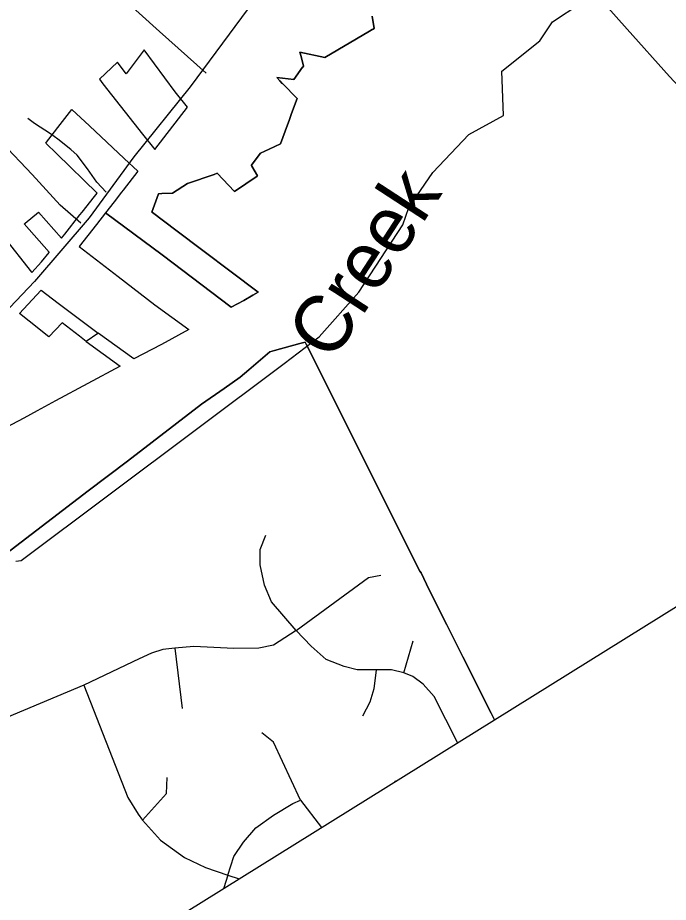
# Model space of a CAD drawing. Extents: x 2001466 to 31450019, y -30647475 to 847247.
# Drawn here: x 31439858 to 31443289, y -30638655 to -30633991 of the extents above; entities that cross this region are included whole.
import ezdxf

# ---------------------------------------------------------------- set-up
doc = ezdxf.new("R2010")
doc.units = 0
for name, color, linetype in [('Exist Boundary Political City Limit New', 7, 'Continuous'), ('Exist Boundary Political City Limit New Hole', 7, 'Continuous'), ('Exist Hydrographic Creek Single Shore', 7, 'Continuous'), ('Exist Hydrographic Creek Single Shore Label', 7, 'Continuous'), ('Exist Road Non-System Type 51', 7, 'Continuous'), ('Exist Road Secondary Type 51 Attributed', 7, 'Continuous'), ('Map Preparation Boundary City Limit Buffer Line', 7, 'Continuous')]:
    doc.layers.add(name, color=color, linetype=linetype)

msp = doc.modelspace()

# ---------------------------------------------------------------- linework, layer by layer
at = {"layer": 'Exist Boundary Political City Limit New'}
for points in [[(31442371.7, -30637692.6), (31450018.8, -30632929.3), (31449005.2, -30631302)], [(31441727.3, -30633982.6), (31441736.9, -30634048.1), (31441729.1, -30634052.7), (31441727.8, -30634053.5), (31441712.5, -30634062.5), (31441478.3, -30634200.5), (31441346.1, -30634172.8), (31441352.3, -30634196), (31441365.3, -30634245.8), (31441361.5, -30634251.1), (31441360.5, -30634252.3), (31441313.5, -30634317.4), (31441224.1, -30634306.8), (31441240, -30634323.2), (31441253.3, -30634336.9), (31441253.8, -30634337.5), (31441330.8, -30634417.4), (31441302, -30634496.6), (31441288.9, -30634532.5), (31441280.3, -30634556.4), (31441244.4, -30634655.1), (31441183.5, -30634684.1), (31441138.8, -30634705.5), (31441089.6, -30634769.3), (31441091.5, -30634772.6), (31441092.1, -30634773.6), (31441122, -30634824.6), (31441120.9, -30634825.5), (31441120.1, -30634826), (31441001, -30634907.8), (31440910.6, -30634811.3), (31440894, -30634816.9), (31440753.4, -30634864.3), (31440674.6, -30634915.6), (31440617.8, -30634918.4), (31440601.3, -30634919.1), (31440566.1, -30635016.3), (31440568.1, -30635017.8), (31440569.3, -30635018.6), (31440691, -30635110.8), (31441126, -30635438.1), (31441098, -30635454), (31441049.6, -30635481.5), (31440983.1, -30635516.6), (31440619.9, -30635241.8), (31440321.5, -30635019.1)], [(31440321.5, -30635019.1), (31440273.5, -30635080.9), (31440228.3, -30635139.1), (31440182.4, -30635197.6), (31440388.6, -30635355.6), (31440581.3, -30635505), (31440759.6, -30635635.8), (31440615.4, -30635714), (31440470.1, -30635790.3), (31440283.1, -30635654.7)], [(31440219.9, -30635698.3), (31440218.8, -30635697.5), (31440183.3, -30635670.6), (31440092, -30635599.9), (31440021.6, -30635674.3), (31439918.1, -30635591.6), (31439866.9, -30635550.6), (31439933.9, -30635479), (31439982.4, -30635427.1), (31440071.5, -30635495.8)], [(31440071.5, -30635495.8), (31440275.8, -30635649.2), (31440283.1, -30635654.7)], [(31440283.1, -30635654.7), (31440280.6, -30635656.8), (31440219.9, -30635698.3)], [(31440283.1, -30635654.7), (31440280.6, -30635656.8), (31440219.9, -30635698.3)], [(31440219.9, -30635698.3), (31440397.5, -30635828.4), (31440057.9, -30636011.1), (31439961.4, -30636063.5), (31439889.5, -30636102.2), (31439606.1, -30636252.6), (31439183.6, -30636480)], [(31439738.4, -30636859.9), (31440229.4, -30636486.1), (31440436.1, -30636328.8), (31440827.3, -30636029.1), (31440945.9, -30635946.1), (31441031.1, -30635886.5), (31441076.3, -30635847.9), (31441188, -30635752.2), (31441212, -30635745.6), (31441344.9, -30635708.8), (31441373.5, -30635700.9), (31441379.3, -30635712.5), (31441450.9, -30635855.5), (31441623.4, -30636200.1), (31441764.4, -30636481.2), (31441884.3, -30636720.6), (31441978.5, -30636908.8), (31441985.4, -30636918.8), (31442028, -30637007.8), (31442120.5, -30637192.3), (31442205.3, -30637361.5), (31442260.8, -30637471.8), (31442309.1, -30637568.2), (31442354.1, -30637657.6), (31442371.7, -30637692.6)]]:
    msp.add_lwpolyline(points, dxfattribs=at)
at = {"layer": 'Exist Boundary Political City Limit New Hole'}
msp.add_lwpolyline([(31440524.4, -30634160.1), (31440430.6, -30634286.6), (31440384.9, -30634225.8), (31440288.5, -30634315.6), (31440307, -30634340.1), (31440516.3, -30634605.1), (31440580.3, -30634685.9), (31440752.8, -30634462), (31440688.3, -30634381.6), (31440524.4, -30634160.1)], dxfattribs=at)
at = {"layer": 'Exist Hydrographic Creek Single Shore'}
for points in [[(31442411.4, -30634272.9), (31442611.3, -30634113), (31442678.4, -30634012.6), (31442827.5, -30633914)], [(31441888.5, -30635082.5), (31441921.3, -30634991.3), (31442046.4, -30634806.8), (31442237.5, -30634607.3), (31442420.4, -30634506.1), (31442411.4, -30634272.9)], [(31441262.3, -30635813.4), (31441448.5, -30635673.9), (31441656.4, -30635438.7), (31441888.5, -30635082.5)], [(31439849, -30636856.7), (31439875.5, -30636852.5), (31441262.3, -30635813.4)]]:
    msp.add_lwpolyline(points, dxfattribs=at)
at = {"layer": 'Exist Road Non-System Type 51'}
for points in [[(31439889.6, -30633577), (31439903.5, -30633567.1), (31439954.6, -30633548.8), (31439988.5, -30633544.5), (31440014.3, -30633550), (31440093.4, -30633598), (31440193.9, -30633688), (31440373.9, -30633853.5), (31440606.2, -30634063), (31440851.1, -30634282.9)], [(31440190.1, -30635074.9), (31440081.1, -30634979.4), (31439934.4, -30634818.4), (31439773.8, -30634649.1), (31439656.4, -30634524.7)], [(31440324.4, -30634911.2), (31440275.4, -30634858.2), (31440226.9, -30634787.2), (31440172.3, -30634716.1), (31440139, -30634685.4), (31440070.1, -30634632), (31440030.7, -30634603.2), (31439945.8, -30634549.5), (31439912.3, -30634522.8)], [(31441327, -30637221.7), (31441196.6, -30637071.1), (31441159, -30636983.2), (31441136.4, -30636875.3), (31441136.4, -30636795), (31441166.5, -30636719.7)], [(31441327, -30637221.7), (31441708.2, -30636943.1), (31441773.4, -30636930.5)], [(31441327, -30637221.7), (31441206.6, -30637299.4), (31441128.9, -30637314.5), (31440998.5, -30637317), (31440786.3, -30637307), (31440686, -30637314.5)], [(31441748.3, -30637429.9), (31441648, -30637429.9), (31441580.3, -30637412.4), (31441485, -30637374.7), (31441404.7, -30637304.5), (31441327, -30637221.7)], [(31441893.8, -30637445), (31441943.9, -30637276.9)], [(31440686, -30637314.5), (31440623.3, -30637322), (31440563.1, -30637342.1), (31440497.9, -30637372.2), (31440206.5, -30637510.3)], [(31440686, -30637314.5), (31440726.1, -30637633.2)], [(31441748.3, -30637429.9), (31441735.8, -30637530.3), (31441715.7, -30637600.6), (31441675.6, -30637673.4)], [(31441893.8, -30637445), (31441828.6, -30637429.9), (31441748.3, -30637429.9)], [(31442177.3, -30637813.6), (31442054.3, -30637570.5), (31441996.6, -30637505.2), (31441941.4, -30637465.1), (31441893.8, -30637445)], [(31440206.5, -30637510.3), (31439657.3, -30637741.1), (31439574.5, -30637768.7), (31439476.7, -30637798.9), (31439239.5, -30637845)], [(31440206.5, -30637510.3), (31440438.7, -30638102.5), (31440493.9, -30638190.4), (31440516.4, -30638223)], [(31441349.1, -30638117.6), (31441206.1, -30637811.4), (31441145.9, -30637761.2)], [(31440516.4, -30638223), (31440641.8, -30638082.4), (31440646.9, -30637997.1)], [(31441849.5, -30638017.8), (31441846.1, -30638014.7)], [(31440965.4, -30638511.6), (31440998, -30638413.7), (31441048.1, -30638338.4), (31441113.3, -30638263.1), (31441206.1, -30638195.4), (31441308.9, -30638135.2), (31441349.1, -30638117.6)], [(31441349.1, -30638117.6), (31441460.2, -30638260.3)], [(31440516.4, -30638223), (31440611.7, -30638328.4), (31440737.1, -30638418.7), (31440847.5, -30638471.4), (31440965.4, -30638511.6)], [(31440965.4, -30638511.6), (31440944.3, -30638579.4), (31440944, -30638581.9)], [(31440965.4, -30638511.6), (31441025.1, -30638531.3)]]:
    msp.add_lwpolyline(points, dxfattribs=at)
at = {"layer": 'Exist Road Secondary Type 51 Attributed'}
for points in [[(31441775.8, -30632944.3), (31441663.1, -30633133.5), (31441421.7, -30633512), (31441072.5, -30633942.8), (31440768.3, -30634355.1), (31440470.6, -30634724.7), (31440235.6, -30635046.8), (31439945.9, -30635381.8), (31439587, -30635759.4), (31439419.6, -30635923.7), (31439113.9, -30636184.6), (31438904.6, -30636324.7), (31438702.3, -30636439.9), (31438554.9, -30636541.1)], [(31441775.8, -30632944.3), (31442248.9, -30633253.5), (31442475.6, -30633406.6), (31442627.1, -30633553.8), (31442739.7, -30633676.8), (31443072.2, -30634050.8), (31443294.5, -30634301.4), (31443468.2, -30634486.4), (31443851, -30634906.2), (31444296, -30635391.3)]]:
    msp.add_lwpolyline(points, dxfattribs=at)
at = {"layer": 'Map Preparation Boundary City Limit Buffer Line'}
msp.add_line((31440099.4, -30639108), (31442371.7, -30637692.6), dxfattribs=at)
for points in [[(31442371.7, -30637692.6), (31450018.8, -30632929.3), (31449005.2, -30631302)], [(31440321.5, -30635019.1), (31440619.9, -30635241.8), (31440983.1, -30635516.6), (31441049.6, -30635481.5), (31441098, -30635454), (31441126, -30635438.1), (31440691, -30635110.8), (31440569.3, -30635018.6), (31440568.1, -30635017.8), (31440566.1, -30635016.3), (31440601.3, -30634919.1), (31440617.8, -30634918.4), (31440674.6, -30634915.6), (31440753.4, -30634864.3), (31440894, -30634816.9), (31440910.6, -30634811.3), (31441001, -30634907.8), (31441120.1, -30634826), (31441120.9, -30634825.5), (31441122, -30634824.6), (31441092.1, -30634773.6), (31441091.5, -30634772.6), (31441089.6, -30634769.3), (31441138.8, -30634705.5), (31441183.5, -30634684.1), (31441244.4, -30634655.1), (31441280.3, -30634556.4), (31441288.9, -30634532.5), (31441302, -30634496.6), (31441330.8, -30634417.4), (31441253.8, -30634337.5), (31441253.3, -30634336.9), (31441240, -30634323.2), (31441224.1, -30634306.8), (31441313.5, -30634317.4), (31441360.5, -30634252.3), (31441361.5, -30634251.1), (31441365.3, -30634245.8), (31441352.3, -30634196), (31441346.1, -30634172.8), (31441478.3, -30634200.5), (31441712.5, -30634062.5), (31441727.8, -30634053.5), (31441729.1, -30634052.7), (31441736.9, -30634048.1), (31441727.3, -30633982.6)], [(31441727.3, -30633982.6), (31441736.9, -30634048.1), (31441729.1, -30634052.7), (31441727.8, -30634053.5), (31441712.5, -30634062.5), (31441478.3, -30634200.5), (31441346.1, -30634172.8), (31441352.3, -30634196), (31441365.3, -30634245.8), (31441361.5, -30634251.1), (31441360.5, -30634252.3), (31441313.5, -30634317.4), (31441224.1, -30634306.8), (31441240, -30634323.2), (31441253.3, -30634336.9), (31441253.8, -30634337.5), (31441330.8, -30634417.4), (31441302, -30634496.6), (31441288.9, -30634532.5), (31441280.3, -30634556.4), (31441244.4, -30634655.1), (31441183.5, -30634684.1), (31441138.8, -30634705.5), (31441089.6, -30634769.3), (31441091.5, -30634772.6), (31441092.1, -30634773.6), (31441122, -30634824.6), (31441120.9, -30634825.5), (31441120.1, -30634826), (31441001, -30634907.8), (31440910.6, -30634811.3), (31440894, -30634816.9), (31440753.4, -30634864.3), (31440674.6, -30634915.6), (31440617.8, -30634918.4), (31440601.3, -30634919.1), (31440566.1, -30635016.3), (31440568.1, -30635017.8), (31440569.3, -30635018.6), (31440691, -30635110.8), (31441126, -30635438.1), (31441098, -30635454), (31441049.6, -30635481.5), (31440983.1, -30635516.6), (31440619.9, -30635241.8), (31440321.5, -30635019.1)], [(31440524.4, -30634160.1), (31440430.6, -30634286.6), (31440384.9, -30634225.8), (31440288.5, -30634315.6), (31440307, -30634340.1), (31440516.3, -30634605.1), (31440580.3, -30634685.9), (31440752.8, -30634462), (31440688.3, -30634381.6), (31440524.4, -30634160.1)], [(31439780.5, -30635143.3), (31439931.4, -30635333.5), (31439932, -30635334.3), (31439984, -30635277.3), (31440024.6, -30635229.3), (31440023.6, -30635228), (31439892.6, -30635078), (31439896.5, -30635074.8), (31439968, -30635016.4), (31440089.5, -30635152.5), (31440106.5, -30635132.5), (31440185.6, -30635031.1), (31440197.4, -30635016.3), (31440263.6, -30634933.2), (31440276.9, -30634916.6), (31440064.9, -30634709.3), (31440006.1, -30634651.9), (31440009.8, -30634647.2), (31440082.1, -30634553.6), (31440143.8, -30634474.1), (31440237.1, -30634561.5), (31440419.8, -30634732.5), (31440491.5, -30634800.3), (31440413.5, -30634901.1), (31440405.6, -30634911.1), (31440365.9, -30634962.1), (31440321.5, -30635019.1)], [(31440321.5, -30635019.1), (31440273.5, -30635080.9), (31440228.3, -30635139.1), (31440182.4, -30635197.6), (31440388.6, -30635355.6), (31440581.3, -30635505), (31440759.6, -30635635.8), (31440615.4, -30635714), (31440470.1, -30635790.3), (31440283.1, -30635654.7)], [(31440219.9, -30635698.3), (31440218.8, -30635697.5), (31440183.3, -30635670.6), (31440092, -30635599.9), (31440021.6, -30635674.3), (31439918.1, -30635591.6), (31439866.9, -30635550.6), (31439933.9, -30635479), (31439982.4, -30635427.1), (31440071.5, -30635495.8)], [(31440071.5, -30635495.8), (31440275.8, -30635649.2), (31440283.1, -30635654.7)], [(31440283.1, -30635654.7), (31440280.6, -30635656.8), (31440219.9, -30635698.3)], [(31440283.1, -30635654.7), (31440280.6, -30635656.8), (31440219.9, -30635698.3)], [(31440219.9, -30635698.3), (31440397.5, -30635828.4), (31440057.9, -30636011.1), (31439961.4, -30636063.5), (31439889.5, -30636102.2), (31439606.1, -30636252.6), (31439183.6, -30636480)], [(31442371.7, -30637692.6), (31442354.1, -30637657.6), (31442309.1, -30637568.2), (31442260.8, -30637471.8), (31442205.3, -30637361.5), (31442120.5, -30637192.3), (31442028, -30637007.8), (31441985.4, -30636918.8), (31441978.5, -30636908.8), (31441884.3, -30636720.6), (31441764.4, -30636481.2), (31441623.4, -30636200.1), (31441450.9, -30635855.5), (31441379.3, -30635712.5), (31441373.5, -30635700.9), (31441344.9, -30635708.8), (31441212, -30635745.6), (31441188, -30635752.2), (31441076.3, -30635847.9), (31441031.1, -30635886.5), (31440945.9, -30635946.1), (31440827.3, -30636029.1), (31440436.1, -30636328.8), (31440229.4, -30636486.1), (31439738.4, -30636859.9)], [(31439738.4, -30636859.9), (31440229.4, -30636486.1), (31440436.1, -30636328.8), (31440827.3, -30636029.1), (31440945.9, -30635946.1), (31441031.1, -30635886.5), (31441076.3, -30635847.9), (31441188, -30635752.2), (31441212, -30635745.6), (31441344.9, -30635708.8), (31441373.5, -30635700.9), (31441379.3, -30635712.5), (31441450.9, -30635855.5), (31441623.4, -30636200.1), (31441764.4, -30636481.2), (31441884.3, -30636720.6), (31441978.5, -30636908.8), (31441985.4, -30636918.8), (31442028, -30637007.8), (31442120.5, -30637192.3), (31442205.3, -30637361.5), (31442260.8, -30637471.8), (31442309.1, -30637568.2), (31442354.1, -30637657.6), (31442371.7, -30637692.6)]]:
    msp.add_lwpolyline(points, dxfattribs=at)

# ---------------------------------------------------------------- texts
at = {"layer": 'Exist Hydrographic Creek Single Shore Label'}
msp.add_text('Creek', height=300, rotation=56.904, dxfattribs=at).set_placement((31441515.3, -30635812.5))

doc.saveas('drawing.dxf')
